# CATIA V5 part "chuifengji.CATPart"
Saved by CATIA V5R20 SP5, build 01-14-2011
Part number: 吹风机
Material "Plastic": density 1200 kg/m3, Young's modulus 2.2e+09 Pa, Poisson ratio 0.38, thermal expansion 6.84e-05 1/K
Bounding box of the stored display mesh (mm): x 0 to 281.156, y -175 to 51.138, z -57.396 to 57.396
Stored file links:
  D:\180211226邢玉磊\chuifengji.CATPart
  C:\Program Files\Dassault Systemes\B20\intel_a\startup\materials\Catalog.CATMaterial
  C:\Program Files\Dassault Systemes\B20\intel_a\startup\materials\DS_star.jpg
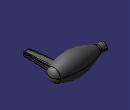
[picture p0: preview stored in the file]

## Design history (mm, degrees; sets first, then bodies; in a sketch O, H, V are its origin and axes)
Body1 (main body), material "Plastic"
  Sketch1 on xy-plane, origin (0, 0, 0), H (1, 0, 0), V (0, 1, 0)
    point P1 (0, -20)
    line L1 (0, -20) -> (28, -20)
    arc A1 centre (28, -45) radius 25 from (28, -20) to (38.6174, -22.3666) cw
    arc A2 centre (166.0263, 249.2342) radius 300 from (38.6174, -22.3666) to (262, -35) ccw
    point P6 (262, -35)
    distance P1 H = 20
    distance P6 H = 35
    length L1 = 28
    radius A1 = 25
    radius A2 = 300
    distance V P6 = 262
    coincidence: P1 V
    horizontal: L1 H
    tangency: A1 L1, A2 A1
  Point1: type OnCurve, Support Sketch1, Ratio 0.6
  MultiSel1
  Plane1: type OffsetPt, RefPlane yz-plane, RefPoint vertex [element of Sketch1 | element of Sketch1]
  Plane2: type OffsetPt, RefPlane yz-plane, RefPoint Point1
  Plane3: type OffsetPt, RefPlane yz-plane, RefPoint Sketch1.P6
  Sketch2 on yz-plane, origin (0, 0, 0), H (0, 1, 0), V (0, 0, 1)
    arc A1 centre (0, 0) radius 20 from (-20, 0) to (20, 0) cw
    point P1 (0, 0)
    point P2 (0, 20)
    point P3 (-20, 0)
    point P4 (20, 0)
    reference projected point E1 (20, 0) from vertex of MultiSel1
    reference projected point E2 (-20, 0) from Sketch1.P1
    coincidence: A1 P2, P2 V, P4 E1, P3 E2, P1 H
  Sketch3 on Plane1, origin (28, 0, 0), H (0, 1, 0), V (0, 0, 1)
    projected arc E1 centre (0, 0) radius 20 from (20, 0) to (-20, 0) ccw from Sketch2.A1
  Sketch4 on Plane2, origin (156.4212, 0, 0), H (0, 1, 0), V (0, 0, 1)
    arc A1 centre (0, 6.2786) radius 51 from (-50.612, 0) to (50.612, 0) cw
    point P2 (-50.612, 0)
    point P3 (50.612, 0)
    reference projected point E1 (-50.612, 0) from Point1
    reference projected point E2 (50.612, 0) from {symmetry ToTransfor Point1, Reference zx-plane}
    radius A1 = 51
    coincidence: P2 H, P2 E1, P3 E2
  Sketch5 on Plane3, origin (262, 0, 0), H (0, 1, 0), V (0, 0, 1)
    arc A1 centre (0, 0) radius 35 from (-35, 0) to (35, 0) cw
    point P2 (-35, 0)
    point P3 (0, 35)
    point P4 (35, 0)
    reference projected point E1 (-35, 0) from Sketch1.P6
    reference projected point E2 (35, 0) from vertex of MultiSel1
    radius A1 = 35
    coincidence: P2 H, A1 P3, P3 V, E1 P2, P4 E2
  Loft1: Sections (Sketch2; Sketch3; Sketch4; Sketch5), Guides (Sketch1; {symmetry ToTransfor Sketch1, Reference zx-plane})
  Sketch6 on xy-plane, origin (0, 0, 0), H (1, 0, 0), V (0, 1, 0)
    arc A1 centre (239.3922, 0) radius 41.6667 from (262, 35) to (262, -35) cw
    point P2 (262, 35)
    point P3 (262, -35)
    reference projected point E1 (262, 35) from vertex of MultiSel1
    reference projected point E2 (262, -35) from Sketch1.P6
    coincidence: P2 E1, P3 E2
  Blend1: StartLimit {blendlimit Curve Sketch5, Support Loft1}, EndLimit {blendlimit Curve Sketch6}
  Sketch7 on xy-plane, origin (0, 0, 0), H (1, 0, 0), V (0, 1, 0)
    line L1 (247, 0) -> (247, -175)
    point P1 (247, 0)
    point P2 (247, -175)
    arc A1 centre (1406.3442, -39.6662) radius 1200 from (207, 0) to (214, -175) ccw
    point P4 (207, 0)
    point P5 (214, -175)
    length L1 = 175
    distance P5 P2 = 33
    distance P4 P1 = 40
    radius A1 = 1200
    distance P5 H = 175
    distance P5 V = 214
    coincidence: P1 H, P4 H
    vertical: L1 V
  Sketch8 on zx-plane, origin (0, 0, 0), H (-1, 0, 0), V (0, 0, 1)
    point P1 (-247, 0)
    line L1 (-247, 0) -> (-247, 15.3025)
    line L2 (-243, 19.3025) -> (-211, 19.3025)
    line L3 (-207, 15.3025) -> (-207, 0)
    point P2 (-207, 0)
    reference projected point E1 (-247, 0) from Sketch7.P1
    reference projected point E2 (-207, 0) from Sketch7.P4
    arc A1 centre (-211, 15.3025) radius 4 from (-207, 15.3025) to (-211, 19.3025) ccw
    arc A2 centre (-243, 15.3025) radius 4 from (-243, 19.3025) to (-247, 15.3025) ccw
    radius A1 = 4
    radius A2 = 4
    coincidence: P1 H, P2 H, P1 E1, P2 E2
    vertical: L1 V, L3 V
    horizontal: L2 H
    tangency: A1 L3, A1 L2, A2 L2, A2 L1
  Plane4: type OffsetPt, RefPlane zx-plane, RefPoint Sketch7.P5
  Sketch9 on Plane4, origin (0, -175, 0), H (-1, 0, 0), V (0, 0, 1)
    point P1 (-247, 0)
    line L1 (-247, 0) -> (-247, 6)
    line L2 (-245, 8) -> (-216, 8)
    line L3 (-214, 6) -> (-214, 0)
    point P2 (-214, 0)
    reference projected point E1 (-247, 0) from Sketch7.P2
    reference projected point E2 (-214, 0) from Sketch7.P5
    arc A1 centre (-216, 6) radius 2 from (-214, 6) to (-216, 8) ccw
    arc A2 centre (-245, 6) radius 2 from (-247, 6) to (-245, 8) cw
    reference projected line E3 (-38.6174, 0) -> (-262, 0) from edge of MultiSel1
    radius A1 = 2
    radius A2 = 2
    distance L2 E3 = 8
    coincidence: P1 H, P2 H, E1 P1, P2 E2
    vertical: L1 V, L3 V
    horizontal: L2 H
    tangency: A1 L3, A1 L2, A2 L1, A2 L2
  Join1: Elements (Loft1; Blend1)
  Line1: stored without definition
  Circle1: stored without definition
  Loft2: Sections (Sketch8; Sketch9), Guides (Circle1; Line1)
  Sketch10 on Plane4, origin (0, -175, 0), H (-1, 0, 0), V (0, 0, 1)
    line L1 (-214, 0) -> (-227, 0)
    point P1 (-214, 0)
    point P2 (-247, 0)
    arc A1 centre (-232, 0) radius 5 from (-227, 0) to (-237, 0) ccw
    point P3 (-232, 0)
    point P4 (-237, 0)
    reference projected point E1 (-247, 0) from Sketch7.P2
    reference projected point E2 (-214, 0) from Sketch7.P5
    line L2 (-237, 0) -> (-247, 0)
    reference projected point E3 (-247, 0) from Sketch7.P2
    radius A1 = 5
    distance E3 P3 = 15
    coincidence: P1 H, L1 P4, P2 E1, P1 E2, L1 P3, L1 L2
    horizontal: L1 H, L2 H
  Fill1: Boundary (Sketch9; Sketch10)
  Join2: Elements (Loft2; Fill1)
  Sketch11 on zx-plane, origin (0, 0, 0), H (-1, 0, 0), V (0, 0, 1)
    point P1 (-207, 0)
    line L1 (-207, 0) -> (-207, -11.9938)
    line L2 (-211, -15.9938) -> (-243, -15.9938)
    line L3 (-247, -11.9938) -> (-247, 0)
    point P2 (-247, 0)
    arc A1 centre (-211, -11.9938) radius 4 from (-207, -11.9938) to (-211, -15.9938) cw
    arc A2 centre (-243, -11.9938) radius 4 from (-247, -11.9938) to (-243, -15.9938) ccw
    reference projected point E1 (-207, 0) from Sketch7.P4
    reference projected point E2 (-247, 0) from Sketch7.P1
    radius A1 = 4
    radius A2 = 4
    coincidence: P1 H, P2 H, P1 E1, E2 P2
    vertical: L1 V, L3 V
    horizontal: L2 H
    tangency: A1 L1, A1 L2, A2 L3, A2 L2
  Sketch12 on Plane1, origin (28, 0, 0), H (0, 1, 0), V (0, 0, 1)
    arc A1 centre (0, 0) radius 20 from (20, 0) to (-20, 0) cw
    point P1 (0, 0)
    point P2 (20, 0)
    point P3 (0, -20)
    point P4 (-20, 0)
    reference projected point E1 (20, 0) from vertex [face of MultiSel1 | face of MultiSel1]
    reference projected point E2 (-20, 0) from vertex [element of Sketch1 | element of Sketch1]
    coincidence: P2 H, A1 P3, P3 V, P4 H, P2 E1, P4 E2, P1 H
  Sketch13 on yz-plane, origin (0, 0, 0), H (0, 1, 0), V (0, 0, 1)
    projected arc E1 centre (0, 0) radius 20 from (-20, 0) to (20, 0) ccw from Sketch12.A1
  Sketch14 on Plane2, origin (156.4212, 0, 0), H (0, 1, 0), V (0, 0, 1)
    arc A1 centre (0, -6.2786) radius 51 from (-50.612, 0) to (50.612, 0) ccw
    point P2 (-50.612, 0)
    point P3 (0, -57.2786)
    point P4 (50.612, 0)
    reference projected point E1 (50.612, 0) from {symmetry ToTransfor Point1, Reference zx-plane}
    reference projected point E2 (-50.612, 0) from Point1
    radius A1 = 51
    coincidence: P2 H, A1 P3, P3 V, P4 E1, P2 E2
  Sketch15 on Plane3, origin (262, 0, 0), H (0, 1, 0), V (0, 0, 1)
    arc A1 centre (0, 0) radius 35 from (-35, 0) to (35, 0) ccw
    point P2 (-35, 0)
    point P3 (0, -35)
    point P4 (35, 0)
    reference projected point E1 (35, 0) from vertex of MultiSel1
    reference projected point E2 (-35, 0) from Sketch1.P6
    reference projected arc E3 centre (0, -6.2786) radius 51 from (-51, -6.2786) to (51, -6.2786) ccw from Sketch14.A1
    radius A1 = 35
    radius E3 = 51 (reference)
    coincidence: P2 H, A1 P3, P3 V, P4 E1, E2 P2
  Loft3: Sections (Sketch13; Sketch12; Sketch14; Sketch15), Guides ({symmetry ToTransfor Sketch1, Reference zx-plane}; Sketch1)
  Blend2: StartLimit {blendlimit Curve Sketch15, Support Loft3}, EndLimit {blendlimit Curve Sketch6}
  Join3: Elements (Loft3; Blend2)
  Sketch16 on Plane4, origin (0, -175, 0), H (-1, 0, 0), V (0, 0, 1)
    point P1 (-214, 0)
    line L1 (-214, 0) -> (-214, -6.4558)
    line L2 (-216, -8.4558) -> (-245, -8.4558)
    line L3 (-247, -6.4558) -> (-247, 0)
    point P2 (-247, 0)
    reference projected point E1 (-247, 0) from Sketch7.P2
    reference projected point E2 (-214, 0) from Sketch7.P5
    arc A1 centre (-245, -6.4558) radius 2 from (-247, -6.4558) to (-245, -8.4558) ccw
    arc A2 centre (-216, -6.4558) radius 2 from (-214, -6.4558) to (-216, -8.4558) cw
    radius A1 = 2
    radius A2 = 2
    coincidence: P1 H, P2 H, P2 E1, E2 P1
    vertical: L1 V, L3 V
    horizontal: L2 H
    tangency: A1 L3, A1 L2, A2 L1, A2 L2
  Fill2: Boundary ({fillboundary BoundaryWire Sketch10, Support Plane4}; Sketch16)
  Loft4: Sections (Sketch16; Sketch11), Guides (Line1; Circle1)
  Trim1: Trimmed (Join1; Join2)
  Trim2: Trimmed (Join3; Loft4)
  Sketch17 on yz-plane, origin (0, 0, 0), H (0, 1, 0), V (0, 0, 1)
    circle A1 centre (0, 0) radius 20
  Pad1: profile Sketch17, direction (1, 0, 0), length 200
  Sketch18 on yz-plane, origin (0, 0, 0), H (0, 1, 0), V (0, 0, 1)
    circle A1 centre (0, 0) radius 17.5
    radius A1 = 17.5
  Pocket1: profile Sketch18, direction (1, 0, 0), length 200
  Sketch19 on xy-plane, origin (0, 0, 0), H (1, 0, 0), V (0, 1, 0)
    line L1 (220, -62.5684) -> (207.8321, -62.5684)
    line L2 (201.8321, -68.5684) -> (201.8321, -76.4648)
    line L3 (207.8321, -82.4648) -> (220, -82.4648)
    line L4 (220, -82.4648) -> (220, -62.5684)
    arc A1 centre (207.8321, -68.5684) radius 6 from (207.8321, -62.5684) to (201.8321, -68.5684) ccw
    arc A2 centre (207.8321, -76.4648) radius 6 from (207.8321, -82.4648) to (201.8321, -76.4648) cw
    point P9 (220, -92.245)
    line L5 (220, -92.245) -> (207.8321, -92.245)
    line L6 (201.8321, -98.245) -> (201.8321, -104)
    line L7 (207.8321, -110) -> (220, -110)
    line L8 (220, -110) -> (220, -92.245)
    point P10 (201.8321, -110)
    arc A3 centre (207.8321, -104) radius 6 from (207.8321, -110) to (201.8321, -104) cw
    arc A4 centre (207.8321, -98.245) radius 6 from (207.8321, -92.245) to (201.8321, -98.245) ccw
    radius A1 = 6
    radius A2 = 6
    radius A3 = 6
    radius A4 = 6
    horizontal: L1 H, L3 H, L5 H, L7 H
    vertical: L2 V, L4 V, L6 V, L8 V
    tangency: A1 L1, A1 L2, A2 L3, A2 L2, A3 L7, A3 L6, A4 L5, A4 L6
    coincidence: P9 L4, P10 L2, L7 P10, L6 P10
  Pad2: profile Sketch19, direction (0, 0, 1), length 5, mirrored extent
